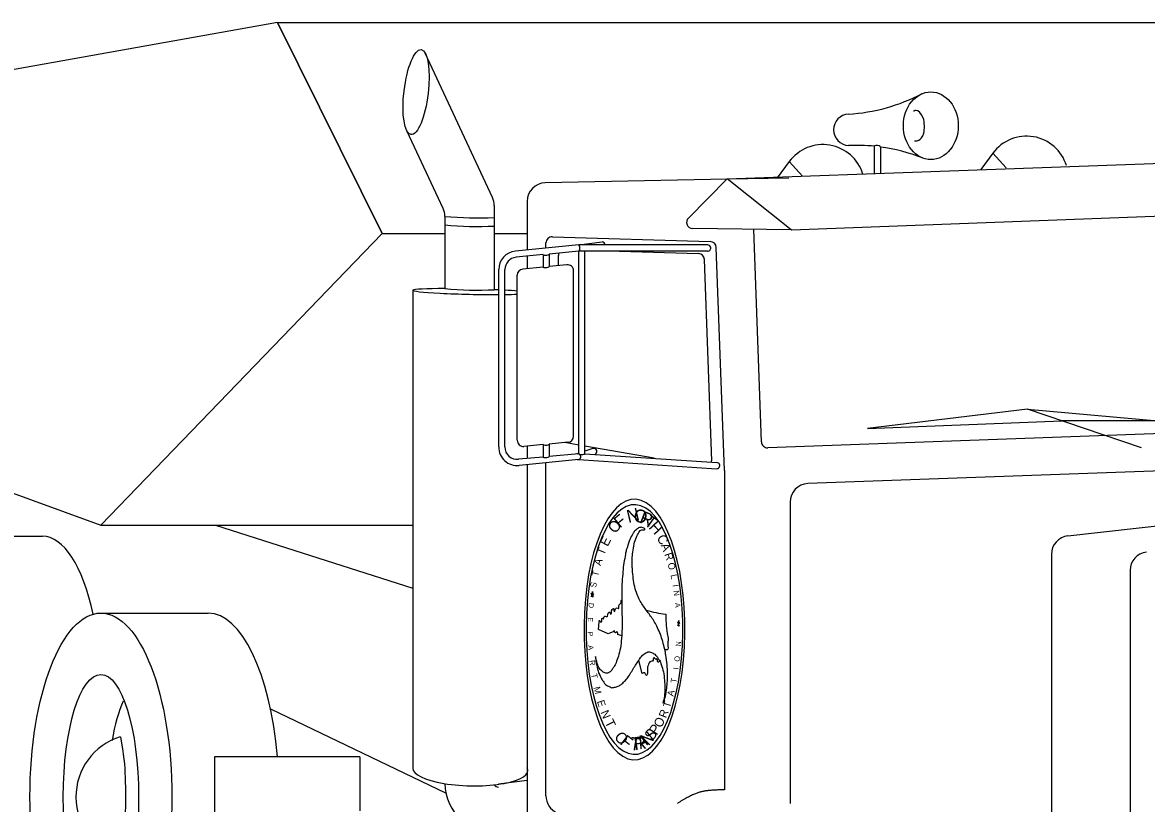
# Model space of a CAD drawing. Extents: x 78728 to 80694, y 10462 to 11664.
# Drawn here: x 79029.11 to 79064.23, y 10658.84 to 10683.23 of the extents above; entities that cross this region are included whole.
import ezdxf

# ---------------------------------------------------------------- set-up
doc = ezdxf.new("R2010")
doc.units = 0
doc.layers.add('Exist Utilities Gas Test Hole SUE LOS A CELL', color=7, linetype='Continuous')

msp = doc.modelspace()

# ---------------------------------------------------------------- linework, layer by layer
at = {"layer": 'Exist Utilities Gas Test Hole SUE LOS A CELL'}
for p, q in [((79037.075, 10683.226), (79016.338, 10679.538)), ((79037.075, 10683.226), (79071.646, 10683.226)), ((79040.34, 10676.633), (79037.075, 10683.226)), ((79037.075, 10683.226), (79040.34, 10676.633)), ((79040.34, 10676.633), (79037.075, 10683.226)), ((79040.34, 10676.633), (79037.075, 10683.226)), ((79037.075, 10683.226), (79040.34, 10676.633)), ((79040.34, 10676.633), (79037.075, 10683.226)), ((79037.075, 10683.226), (79040.34, 10676.633)), ((79043.793, 10677.76), (79041.692, 10682.265)), ((79042.249, 10677.417), (79041.127, 10679.824)), ((79055.72, 10679.36), (79055.72, 10678.506)), ((79055.912, 10679.337), (79055.912, 10678.513)), ((79059.426, 10679.145), (79059.051, 10678.635)), ((79059.426, 10679.145), (79059.839, 10678.689)), ((79051.124, 10678.34), (79066.464, 10678.897)), ((79053.065, 10678.881), (79052.69, 10678.371)), ((79053.065, 10678.881), (79053.479, 10678.425)), ((79051.124, 10678.333), (79045.442, 10678.22)), ((79051.124, 10678.34), (79049.912, 10677.121)), ((79051.124, 10678.34), (79053.053, 10678.378)), ((79053.127, 10676.751), (79051.124, 10678.34)), ((79044.874, 10677.641), (79044.874, 10676.122)), ((79043.847, 10677.515), (79043.847, 10674.882)), ((79053.132, 10676.751), (79068.451, 10677.328)), ((79042.303, 10677.173), (79042.303, 10674.916)), ((79031.557, 10667.532), (79040.34, 10676.633)), ((79040.34, 10676.633), (79042.303, 10676.633)), ((79043.847, 10676.633), (79044.874, 10676.633)), ((79045.662, 10676.536), (79050.597, 10676.387)), ((79053.122, 10676.751), (79050.047, 10676.792)), ((79052.194, 10670.131), (79051.953, 10676.767)), ((79046.486, 10676.28), (79044.508, 10676.086)), ((79045.463, 10676.18), (79045.463, 10676.343)), ((79046.486, 10676.28), (79047.216, 10676.374)), ((79050.508, 10676.28), (79046.486, 10676.28)), ((79051.037, 10669.236), (79050.784, 10676.201)), ((79045.373, 10675.977), (79044.527, 10675.894)), ((79044.874, 10675.928), (79044.874, 10675.54)), ((79045.373, 10675.974), (79045.373, 10675.589)), ((79046.486, 10676.086), (79045.565, 10675.996)), ((79045.566, 10675.992), (79045.566, 10675.608)), ((79045.849, 10675.636), (79045.849, 10675.946)), ((79050.508, 10676.087), (79046.486, 10676.087)), ((79046.486, 10669.759), (79046.486, 10676.086)), ((79046.679, 10669.761), (79046.679, 10676.087)), ((79047.758, 10676.087), (79050.225, 10676.012)), ((79050.64, 10669.542), (79050.412, 10675.826)), ((79043.986, 10669.97), (79043.986, 10675.51)), ((79044.179, 10669.97), (79044.179, 10675.51)), ((79045.373, 10675.589), (79044.739, 10675.527)), ((79046.112, 10675.661), (79045.566, 10675.608)), ((79046.324, 10670.308), (79046.324, 10675.469)), ((79044.565, 10670.182), (79044.565, 10675.335)), ((79041.3, 10674.864), (79041.3, 10659.943)), ((79060.51, 10671.153), (79055.514, 10670.548)), ((79060.51, 10671.153), (79064.582, 10670.783)), ((79064.068, 10669.942), (79060.51, 10671.153)), ((79055.514, 10670.548), (79061.585, 10670.787)), ((79064.582, 10670.783), (79061.585, 10670.787)), ((79066.191, 10670.446), (79052.394, 10669.945)), ((79025.016, 10669.903), (79031.557, 10667.532)), ((79045.373, 10670.044), (79044.775, 10669.99)), ((79044.874, 10669.999), (79044.874, 10669.611)), ((79045.373, 10670.044), (79045.373, 10669.657)), ((79046.149, 10670.116), (79045.566, 10670.062)), ((79045.566, 10670.062), (79045.566, 10669.675)), ((79046.486, 10670.032), (79046.056, 10670.107)), ((79046.927, 10669.919), (79046.677, 10669.84)), ((79048.846, 10669.619), (79046.679, 10669.998)), ((79045.373, 10669.657), (79044.602, 10669.586)), ((79046.486, 10669.576), (79044.621, 10669.394)), ((79046.486, 10669.759), (79045.566, 10669.675)), ((79046.486, 10669.576), (79050.792, 10669.292)), ((79046.678, 10669.757), (79050.805, 10669.485)), ((79044.874, 10669.419), (79044.874, 10657.768)), ((79045.463, 10659.073), (79045.463, 10669.476)), ((79051.037, 10669.236), (79051.037, 10659.263)), ((79068.245, 10669.355), (79053.647, 10668.825)), ((79053.089, 10668.247), (79053.089, 10658.832)), ((79061.769, 10667.193), (79072.393, 10668.379)), ((79031.557, 10667.532), (79041.3, 10667.532)), ((79035.137, 10667.532), (79041.3, 10665.557)), ((79048.558, 10667.408), (79048.555, 10667.401)), ((79048.558, 10667.408), (79048.555, 10667.401)), ((79048.558, 10667.408), (79048.555, 10667.401)), ((79026.38, 10667.183), (79029.731, 10667.183)), ((79061.255, 10666.617), (79061.255, 10656.36)), ((79063.713, 10666.115), (79063.713, 10654.145)), ((79046.897, 10665.355), (79046.877, 10665.405)), ((79046.877, 10665.405), (79046.905, 10665.395)), ((79046.897, 10665.355), (79046.877, 10665.405)), ((79046.877, 10665.405), (79046.905, 10665.395)), ((79046.886, 10665.291), (79046.897, 10665.355)), ((79046.886, 10665.291), (79046.897, 10665.355)), ((79046.909, 10665.326), (79046.886, 10665.291)), ((79046.909, 10665.326), (79046.886, 10665.291)), ((79046.905, 10665.395), (79046.915, 10665.457)), ((79046.905, 10665.395), (79046.915, 10665.457)), ((79046.929, 10665.276), (79046.909, 10665.326)), ((79046.929, 10665.276), (79046.909, 10665.326)), ((79046.915, 10665.457), (79046.921, 10665.389)), ((79046.915, 10665.457), (79046.921, 10665.389)), ((79046.921, 10665.389), (79046.948, 10665.38)), ((79046.921, 10665.389), (79046.948, 10665.38)), ((79046.948, 10665.38), (79046.924, 10665.346)), ((79046.948, 10665.38), (79046.924, 10665.346)), ((79046.924, 10665.346), (79046.929, 10665.276)), ((79046.924, 10665.346), (79046.929, 10665.276)), ((79031.557, 10664.783), (79034.908, 10664.783)), ((79048.598, 10664.874), (79048.598, 10664.874)), ((79048.598, 10664.874), (79048.598, 10664.874)), ((79047.106, 10664.269), (79047.122, 10664.51)), ((79047.106, 10664.269), (79047.122, 10664.51)), ((79047.401, 10664.138), (79047.106, 10664.269)), ((79047.401, 10664.138), (79047.106, 10664.269)), ((79049.599, 10664.493), (79049.572, 10664.503)), ((79049.572, 10664.503), (79049.592, 10664.454)), ((79049.599, 10664.493), (79049.572, 10664.503)), ((79049.572, 10664.503), (79049.592, 10664.454)), ((79049.592, 10664.454), (79049.581, 10664.39)), ((79049.592, 10664.454), (79049.581, 10664.39)), ((79049.581, 10664.39), (79049.604, 10664.424)), ((79049.581, 10664.39), (79049.604, 10664.424)), ((79049.611, 10664.555), (79049.599, 10664.493)), ((79049.611, 10664.555), (79049.599, 10664.493)), ((79049.604, 10664.424), (79049.624, 10664.375)), ((79049.604, 10664.424), (79049.624, 10664.375)), ((79049.617, 10664.487), (79049.611, 10664.555)), ((79049.617, 10664.487), (79049.611, 10664.555)), ((79049.643, 10664.481), (79049.617, 10664.487)), ((79049.643, 10664.481), (79049.617, 10664.487)), ((79049.619, 10664.445), (79049.643, 10664.481)), ((79049.619, 10664.445), (79049.643, 10664.481)), ((79049.624, 10664.375), (79049.619, 10664.445)), ((79049.624, 10664.375), (79049.619, 10664.445)), ((79047.578, 10664.209), (79047.401, 10664.138)), ((79047.578, 10664.209), (79047.401, 10664.138)), ((79047.83, 10664.068), (79047.706, 10664.114)), ((79047.83, 10664.068), (79047.706, 10664.114)), ((79049.791, 10663.734), (79049.791, 10663.734)), ((79049.791, 10663.734), (79049.791, 10663.734)), ((79048.473, 10662.894), (79048.361, 10663.306)), ((79048.361, 10663.306), (79048.361, 10663.306)), ((79048.473, 10662.894), (79048.361, 10663.306)), ((79048.361, 10663.306), (79048.361, 10663.306)), ((79036.855, 10661.795), (79042.339, 10659.164)), ((79035.104, 10660.296), (79035.104, 10655.006)), ((79039.647, 10660.296), (79039.647, 10658.609)), ((79044.874, 10659.555), (79043.98, 10659.444))]:
    msp.add_line(p, q, dxfattribs=at)
msp.add_lwpolyline([(79039.647, 10660.296), (79035.104, 10660.296)], dxfattribs=at)
for centre, radius, start, end in [((79054.579, 10686.031), 5.675, 273.3538, 297.7122), ((79054.94, 10679.876), 0.491, 93.3538, 266.6462), ((79054.117, 10678.107), 1.306, 17.237, 143.6448), ((79055.137, 10673.642), 5.748, 84.1788, 92.2455), ((79055.137, 10673.642), 5.748, 68.6583, 82.2418), ((79060.478, 10678.371), 1.306, 17.237, 143.6448), ((79045.453, 10677.641), 0.579, 91.1393, 180), ((79043.268, 10677.515), 0.579, 0, 25), ((79041.724, 10677.173), 0.579, 0, 25), ((79043.297, 10687.364), 10.24, 264.4273, 273.0751), ((79043.297, 10687.096), 10.24, 264.4273, 273.0751), ((79050.049, 10676.985), 0.193, 135.17, 269.2351), ((79045.656, 10676.343), 0.193, 88.2645, 180), ((79053.124, 10676.944), 0.193, 269.2351, 272.1563), ((79047.211, 10676.278), 0.0965, 1.6997, 86.6572), ((79050.514, 10676.183), 0.0965, 266.2218, 86.2218), ((79050.591, 10676.194), 0.193, 2.0794, 88.2645), ((79044.565, 10675.51), 0.579, 95.5804, 180), ((79044.565, 10675.51), 0.386, 95.5804, 180), ((79046.042, 10675.946), 0.193, 155.6276, 180), ((79050.219, 10675.819), 0.193, 2.0794, 88.2645), ((79044.757, 10675.335), 0.193, 95.5804, 180), ((79046.131, 10675.469), 0.193, 0, 95.5804), ((79043.297, 10685.107), 10.24, 264.4273, 273.0751), ((79046.131, 10670.308), 0.193, 275.2401, 0), ((79044.565, 10669.97), 0.579, 180, 275.5804), ((79044.565, 10669.97), 0.386, 180, 275.5804), ((79044.757, 10670.182), 0.193, 180, 275.2401), ((79046.956, 10669.827), 0.0965, 291.7778, 107.6113), ((79052.387, 10670.138), 0.193, 182.0794, 272.0794), ((79046.458, 10669.665), 0.0926, 266.586, 107.9756), ((79050.447, 10669.535), 0.193, 348.6848, 2.0794), ((79050.798, 10669.388), 0.0965, 266.2218, 86.2218), ((79053.668, 10668.247), 0.579, 92.0794, 180), ((79061.834, 10666.617), 0.579, 96.3744, 180), ((79064.291, 10666.115), 0.579, 96.3744, 180), ((79032.733, 10659.045), 1.958, 106.959, 253.7805), ((79043.985, 10659.512), 1.682, 181.8568, 268.4926), ((79043.985, 10659.512), 0.164, 212.6118, 268.4926), ((79046.042, 10659.073), 0.579, 180, 245.5491)]:
    msp.add_arc(centre, radius, start, end, dxfattribs=at)
for centre, major_axis, ratio in [((79041.405, 10681.052), (0.158, 1.326), 0.283036), ((79057.488, 10680.002), (0, 1.056), 0.8125), ((79031.557, 10659.045), (0, 5.738), 0.386478), ((79031.557, 10659.045), (0, 3.823), 0.307656)]:
    msp.add_ellipse(centre, major_axis=major_axis, ratio=ratio, dxfattribs=at)
for centre, major_axis, ratio, start_param, end_param in [((79055.816, 10679.35), (-0.0966, 0.0108), 0.334654, 3.096038, 6.283185), ((79046.487, 10676.182), (-0.0013, 0.0972), 0.351139, 3.062724, 6.283185), ((79045.47, 10675.982), (0.0975, 0.0055), 0.259529, 3.225171, 6.472122), ((79045.47, 10675.597), (0.0975, 0.0055), 0.259529, 3.225171, 6.472122), ((79043.098, 10674.823), (-1.798, 0.04), 0.046583, 5.1713, 8.375165), ((79043.098, 10674.823), (-1.798, 0.04), 0.046583, 4.195477, 4.283977), ((79043.098, 10674.823), (-1.798, 0.04), 0.046583, 3.752909, 4.070851), ((79043.098, 10674.823), (-1.798, 0.04), 0.046583, 2.213476, 2.527889), ((79045.47, 10670.052), (0.0975, 0.0055), 0.259529, 3.225171, 6.472122), ((79045.471, 10669.665), (0.0975, 0.0055), 0.259529, 3.225171, 6.472122), ((79046.582, 10669.76), (-0.0949, -0.0009), 0.293196, 6.282737, 9.424275), ((79048.228, 10664.27), (0, 4.069), 0.387649, 4.580113, 7.721705), ((79048.228, 10664.27), (0, 4.069), 0.387649, 4.580113, 7.721705), ((79048.228, 10664.27), (0, 3.899), 0.387649, 4.580113, 7.721705), ((79048.228, 10664.27), (0, 3.899), 0.387649, 4.580113, 7.721705), ((79029.731, 10662.535), (0, 4.647), 0.387713, 5.208857, 6.283185), ((79049.533, 10686.19), (0, -21.453), 0.387649, 6.075485, 6.077223), ((79049.533, 10686.19), (0, -21.453), 0.387649, 6.075485, 6.077223), ((79034.908, 10659.045), (0, 5.738), 0.386478, 4.932222, 6.283185), ((79048.228, 10664.27), (0, -4.069), 0.387649, 4.580113, 7.721705), ((79048.228, 10664.27), (0, -4.069), 0.387649, 4.580113, 7.721705), ((79048.228, 10664.27), (0, -3.899), 0.387649, 4.580113, 7.721705), ((79048.228, 10664.27), (0, -3.899), 0.387649, 4.580113, 7.721705), ((79049.533, 10686.19), (0, -21.453), 0.387649, 6.170414, 6.243823), ((79049.533, 10686.19), (0, -21.453), 0.387649, 6.170414, 6.243823), ((79032.923, 10658.9), (0, 3.823), 0.307656, 0.60872, 1.048981), ((79043.098, 10659.903), (-1.798, 0.04), 0.285874, 6.283185, 9.588173)]:
    msp.add_ellipse(centre, major_axis=major_axis, ratio=ratio, start_param=start_param, end_param=end_param, dxfattribs=at)
for points, degree in [([(79057.019, 10680.479), (79057.002, 10680.479), (79056.978, 10680.47), (79056.951, 10680.453)], 2), ([(79057.019, 10680.479), (79057.002, 10680.479), (79056.978, 10680.47), (79056.951, 10680.453)], 2), ([(79056.981, 10679.535), (79056.996, 10679.529), (79057.009, 10679.525), (79057.096, 10679.525), (79057.298, 10679.695), (79057.298, 10680.309), (79057.096, 10680.479), (79057.019, 10680.479)], 3), ([(79056.981, 10679.535), (79056.996, 10679.529), (79057.009, 10679.525), (79057.096, 10679.525), (79057.298, 10679.695), (79057.298, 10680.309), (79057.096, 10680.479), (79057.019, 10680.479)], 3), ([(79032.18, 10657.166), (79032.281, 10657.724), (79032.339, 10658.383), (79032.339, 10659.705), (79032.281, 10660.363), (79032.18, 10660.921)], 3), ([(79032.18, 10657.166), (79032.281, 10657.724), (79032.339, 10658.383), (79032.339, 10659.705), (79032.281, 10660.363), (79032.18, 10660.921)], 3), ([(79051.037, 10659.263), (79050.559, 10659.263), (79050.042, 10659.134), (79049.568, 10658.842)], 2), ([(79051.037, 10659.263), (79050.559, 10659.263), (79050.042, 10659.134), (79049.568, 10658.842)], 2)]:
    msp.add_open_spline(points, degree=degree, dxfattribs=at)
for points in [[(79048.555, 10667.401), (79048.521, 10667.437), (79048.417, 10667.461), (79048.306, 10667.41), (79048.297, 10667.401), (79048.24, 10667.347), (79048.178, 10667.259), (79048.083, 10667.081), (79048.005, 10666.849), (79047.973, 10666.749), (79047.947, 10666.621), (79047.898, 10666.349), (79047.866, 10666.08), (79047.842, 10665.761), (79047.83, 10665.478), (79047.833, 10665.184), (79047.837, 10664.886), (79047.839, 10664.599), (79047.839, 10664.303), (79047.825, 10664.015), (79047.823, 10663.99), (79047.787, 10663.689), (79047.725, 10663.437), (79047.651, 10663.232), (79047.609, 10663.141), (79047.552, 10663.054), (79047.519, 10663.003), (79047.443, 10662.934), (79047.333, 10662.906), (79047.229, 10662.958), (79047.139, 10663.05), (79047.065, 10663.214), (79047.01, 10663.429)], [(79048.555, 10667.401), (79048.521, 10667.437), (79048.417, 10667.461), (79048.306, 10667.41), (79048.297, 10667.401), (79048.24, 10667.347), (79048.178, 10667.259), (79048.083, 10667.081), (79048.005, 10666.849), (79047.973, 10666.749), (79047.947, 10666.621), (79047.898, 10666.349), (79047.866, 10666.08), (79047.842, 10665.761), (79047.83, 10665.478), (79047.833, 10665.184), (79047.837, 10664.886), (79047.839, 10664.599), (79047.839, 10664.303), (79047.825, 10664.015), (79047.823, 10663.99), (79047.787, 10663.689), (79047.725, 10663.437), (79047.651, 10663.232), (79047.609, 10663.141), (79047.552, 10663.054), (79047.519, 10663.003), (79047.443, 10662.934), (79047.333, 10662.906), (79047.229, 10662.958), (79047.139, 10663.05), (79047.065, 10663.214), (79047.01, 10663.429)], [(79049.117, 10661.965), (79049.144, 10662.022), (79049.206, 10662.243), (79049.244, 10662.514), (79049.247, 10662.541), (79049.256, 10662.695), (79049.257, 10662.878), (79049.246, 10663.18), (79049.206, 10663.469), (79049.189, 10663.59), (79049.159, 10663.714), (79049.092, 10663.959), (79049.018, 10664.166), (79048.922, 10664.377), (79048.834, 10664.545), (79048.733, 10664.689), (79048.632, 10664.826), (79048.535, 10664.965), (79048.434, 10665.114), (79048.345, 10665.289), (79048.338, 10665.307), (79048.254, 10665.538), (79048.2, 10665.803), (79048.168, 10666.069), (79048.16, 10666.206), (79048.16, 10666.381), (79048.158, 10666.481), (79048.174, 10666.682), (79048.219, 10666.945), (79048.288, 10667.149), (79048.364, 10667.302), (79048.457, 10667.387), (79048.555, 10667.401), (79048.558, 10667.408)], [(79049.117, 10661.965), (79049.144, 10662.022), (79049.206, 10662.243), (79049.244, 10662.514), (79049.247, 10662.541), (79049.256, 10662.695), (79049.257, 10662.878), (79049.246, 10663.18), (79049.206, 10663.469), (79049.189, 10663.59), (79049.159, 10663.714), (79049.092, 10663.959), (79049.018, 10664.166), (79048.922, 10664.377), (79048.834, 10664.545), (79048.733, 10664.689), (79048.632, 10664.826), (79048.535, 10664.965), (79048.434, 10665.114), (79048.345, 10665.289), (79048.338, 10665.307), (79048.254, 10665.538), (79048.2, 10665.803), (79048.168, 10666.069), (79048.16, 10666.206), (79048.16, 10666.381), (79048.158, 10666.481), (79048.174, 10666.682), (79048.219, 10666.945), (79048.288, 10667.149), (79048.364, 10667.302), (79048.457, 10667.387), (79048.555, 10667.401), (79048.558, 10667.408)], [(79047.122, 10664.51), (79047.12, 10664.534), (79047.137, 10664.555), (79047.179, 10664.493), (79047.204, 10664.535), (79047.205, 10664.584), (79047.225, 10664.627), (79047.255, 10664.601), (79047.287, 10664.681), (79047.312, 10664.688), (79047.365, 10664.67), (79047.436, 10664.811), (79047.463, 10664.812), (79047.467, 10664.766), (79047.483, 10664.753), (79047.517, 10664.877), (79047.525, 10664.894), (79047.577, 10664.927), (79047.588, 10664.899), (79047.589, 10664.838), (79047.595, 10664.824), (79047.613, 10664.848), (79047.639, 10664.912), (79047.682, 10664.952), (79047.727, 10664.922), (79047.74, 10665.016), (79047.798, 10665.091), (79047.812, 10665.143), (79047.818, 10665.2)], [(79047.122, 10664.51), (79047.12, 10664.534), (79047.137, 10664.555), (79047.179, 10664.493), (79047.204, 10664.535), (79047.205, 10664.584), (79047.225, 10664.627), (79047.255, 10664.601), (79047.287, 10664.681), (79047.312, 10664.688), (79047.365, 10664.67), (79047.436, 10664.811), (79047.463, 10664.812), (79047.467, 10664.766), (79047.483, 10664.753), (79047.517, 10664.877), (79047.525, 10664.894), (79047.577, 10664.927), (79047.588, 10664.899), (79047.589, 10664.838), (79047.595, 10664.824), (79047.613, 10664.848), (79047.639, 10664.912), (79047.682, 10664.952), (79047.727, 10664.922), (79047.74, 10665.016), (79047.798, 10665.091), (79047.812, 10665.143), (79047.818, 10665.2)], [(79047.833, 10665.191), (79047.833, 10665.184), (79047.837, 10664.886), (79047.839, 10664.599), (79047.839, 10664.303), (79047.829, 10664.068)], [(79047.833, 10665.191), (79047.833, 10665.184), (79047.837, 10664.886), (79047.839, 10664.599), (79047.839, 10664.303), (79047.829, 10664.068)], [(79049.18, 10663.637), (79049.159, 10663.714), (79049.092, 10663.959), (79049.018, 10664.166), (79048.922, 10664.377), (79048.834, 10664.545), (79048.733, 10664.689), (79048.632, 10664.826), (79048.598, 10664.874)], [(79049.18, 10663.637), (79049.159, 10663.714), (79049.092, 10663.959), (79049.018, 10664.166), (79048.922, 10664.377), (79048.834, 10664.545), (79048.733, 10664.689), (79048.632, 10664.826), (79048.598, 10664.874)], [(79049.206, 10664.754), (79049.214, 10664.477), (79049.253, 10664.141), (79049.279, 10663.956), (79049.27, 10663.807), (79049.248, 10663.633), (79049.18, 10663.638)], [(79049.206, 10664.754), (79049.214, 10664.477), (79049.253, 10664.141), (79049.279, 10663.956), (79049.27, 10663.807), (79049.248, 10663.633), (79049.18, 10663.638)], [(79047.706, 10664.114), (79047.697, 10664.177), (79047.674, 10664.203), (79047.639, 10664.17), (79047.615, 10664.182), (79047.591, 10664.241), (79047.578, 10664.209)], [(79047.706, 10664.114), (79047.697, 10664.177), (79047.674, 10664.203), (79047.639, 10664.17), (79047.615, 10664.182), (79047.591, 10664.241), (79047.578, 10664.209)], [(79047.01, 10663.429), (79047.017, 10663.335), (79047.06, 10663.089), (79047.132, 10662.867), (79047.14, 10662.852), (79047.187, 10662.749), (79047.247, 10662.658), (79047.355, 10662.531), (79047.471, 10662.477), (79047.52, 10662.454), (79047.579, 10662.461), (79047.692, 10662.487), (79047.798, 10662.547), (79047.918, 10662.656), (79048.018, 10662.768), (79048.117, 10662.923), (79048.213, 10663.083), (79048.31, 10663.229), (79048.409, 10663.376), (79048.513, 10663.49), (79048.524, 10663.497), (79048.643, 10663.569), (79048.757, 10663.556), (79048.862, 10663.496), (79048.915, 10663.447), (79048.971, 10663.358), (79049.007, 10663.313), (79049.067, 10663.177), (79049.131, 10662.945), (79049.166, 10662.69), (79049.179, 10662.44), (79049.162, 10662.192), (79049.117, 10661.965)], [(79047.01, 10663.429), (79047.017, 10663.335), (79047.06, 10663.089), (79047.132, 10662.867), (79047.14, 10662.852), (79047.187, 10662.749), (79047.247, 10662.658), (79047.355, 10662.531), (79047.471, 10662.477), (79047.52, 10662.454), (79047.579, 10662.461), (79047.692, 10662.487), (79047.798, 10662.547), (79047.918, 10662.656), (79048.018, 10662.768), (79048.117, 10662.923), (79048.213, 10663.083), (79048.31, 10663.229), (79048.409, 10663.376), (79048.513, 10663.49), (79048.524, 10663.497), (79048.643, 10663.569), (79048.757, 10663.556), (79048.862, 10663.496), (79048.915, 10663.447), (79048.971, 10663.358), (79049.007, 10663.313), (79049.067, 10663.177), (79049.131, 10662.945), (79049.166, 10662.69), (79049.179, 10662.44), (79049.162, 10662.192), (79049.117, 10661.965)], [(79048.361, 10663.306), (79048.409, 10663.376), (79048.513, 10663.49), (79048.524, 10663.497), (79048.643, 10663.569), (79048.757, 10663.556), (79048.862, 10663.496), (79048.915, 10663.447), (79048.971, 10663.358), (79049.005, 10663.315)], [(79048.361, 10663.306), (79048.409, 10663.376), (79048.513, 10663.49), (79048.524, 10663.497), (79048.643, 10663.569), (79048.757, 10663.556), (79048.862, 10663.496), (79048.915, 10663.447), (79048.971, 10663.358), (79049.005, 10663.315)], [(79049.004, 10663.314), (79048.986, 10663.249), (79048.962, 10663.252), (79048.925, 10663.351), (79048.873, 10663.342), (79048.852, 10663.385), (79048.837, 10663.391), (79048.794, 10663.285), (79048.743, 10663.274), (79048.653, 10663.148), (79048.632, 10663.064), (79048.628, 10662.868), (79048.606, 10662.837), (79048.583, 10662.854), (79048.535, 10662.922), (79048.473, 10662.894)], [(79049.004, 10663.314), (79048.986, 10663.249), (79048.962, 10663.252), (79048.925, 10663.351), (79048.873, 10663.342), (79048.852, 10663.385), (79048.837, 10663.391), (79048.794, 10663.285), (79048.743, 10663.274), (79048.653, 10663.148), (79048.632, 10663.064), (79048.628, 10662.868), (79048.606, 10662.837), (79048.583, 10662.854), (79048.535, 10662.922), (79048.473, 10662.894)]]:
    msp.add_spline(points, degree=3, dxfattribs=at)

# ---------------------------------------------------------------- texts
for s, height, rotation, p in [('F', 0.373, 39.1097, (79047.773, 10667.42)), ('N', 0.402, 13.7161, (79048.038, 10667.595)), ('O', 0.406, 354.6138, (79048.191, 10667.63)), ('R', 0.397, 338.4516, (79048.357, 10667.615)), ('T', 0.38, 324.6913, (79048.506, 10667.556)), ('O', 0.345, 49.7958, (79047.621, 10667.243)), ('H', 0.353, 313.1909, (79048.654, 10667.448)), ('E', 0.291, 62.418, (79047.389, 10666.843)), ('C', 0.299, 299.1691, (79048.911, 10667.134)), ('T', 0.26, 67.9156, (79047.277, 10666.57)), ('A', 0.267, 293.0918, (79049.04, 10666.901)), ('A', 0.234, 72.4252, (79047.174, 10666.245)), ('R', 0.241, 288.8431, (79049.159, 10666.621)), ('O', 0.216, 284.78, (79049.259, 10666.329)), ('T', 0.21, 76.2821, (79047.091, 10665.913)), ('L', 0.196, 281.6493, (79049.353, 10665.972)), ('S', 0.191, 79.3756, (79047.025, 10665.565)), ('I', 0.187, 279.7998, (79049.414, 10665.659)), ('N', 0.174, 277.3126, (79049.444, 10665.477)), ('D', 0.162, 266.1987, (79046.803, 10665.106)), ('A', 0.163, 274.263, (79049.492, 10665.098)), ('E', 0.157, 268.6659, (79046.775, 10664.647)), ('P', 0.158, 271.5895, (79046.767, 10664.206)), ('N', 0.159, 87.9128, (79049.676, 10663.74)), ('A', 0.163, 274.1841, (79046.779, 10663.774)), ('R', 0.173, 277.0759, (79046.816, 10663.303)), ('O', 0.165, 85.0401, (79049.636, 10663.26)), ('T', 0.187, 279.976, (79046.871, 10662.878)), ('I', 0.174, 82.9246, (79049.606, 10663.012)), ('M', 0.207, 283.4344, (79046.947, 10662.461)), ('T', 0.185, 80.4753, (79049.536, 10662.59)), ('A', 0.204, 77.1431, (79049.444, 10662.173)), ('E', 0.232, 287.4908, (79047.054, 10662.026)), ('R', 0.255, 69.029, (79049.214, 10661.486)), ('T', 0.23, 72.819, (79049.335, 10661.809)), ('N', 0.26, 291.9267, (79047.163, 10661.689)), ('T', 0.289, 297.1562, (79047.292, 10661.375)), ('O', 0.285, 63.7217, (79049.065, 10661.18)), ('N', 0.372, 38.3334, (79048.595, 10660.621)), ('S', 0.344, 49.2884, (79048.764, 10660.764)), ('P', 0.314, 57.6257, (79048.922, 10660.951)), ('O', 0.348, 311.3467, (79047.573, 10660.9)), ('F', 0.375, 322.4218, (79047.748, 10660.709)), ('T', 0.403, 350.5283, (79048.061, 10660.523)), ('R', 0.405, 8.3495, (79048.239, 10660.499)), ('A', 0.393, 24.4797, (79048.412, 10660.531))]:
    msp.add_text(s, height=height, rotation=rotation, dxfattribs=at).set_placement(p)

doc.saveas('drawing.dxf')
